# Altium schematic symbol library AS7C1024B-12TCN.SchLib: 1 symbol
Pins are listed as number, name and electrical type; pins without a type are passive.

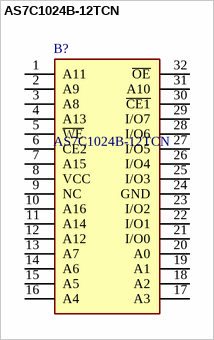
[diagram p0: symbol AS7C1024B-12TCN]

## AS7C1024B-12TCN
designator B?
Industrial and commercial temperatures  Organization: 131,072 words x 8 bits  High speed  10/12/15/20 ns address access time  5/6/7/8 ns output enable access time  Low power consumption: ACTIVE  605 mW / max @ 10 ns  Low power consumption: STANDBY  55 mW / max CMOS  Easy memory expansion with CE1, CE2, OE inputs  TTL/LVTTL-compatible, three-state I/O 32-pin JEDEC standard packages; Manufacturer_Name: Alliance Memory; Geometry.Height: 1.2mm
footprint SOP50P2000X120-32N
pins: 1 A11, 2 A9, 3 A8, 4 A13, 5 ~{WE}, 6 CE2, 7 A15, 8 VCC, 9 NC, 10 A16, 11 A14, 12 A12, 13 A7, 14 A6, 15 A5, 16 A4, 17 A3, 18 A2, 19 A1, 20 A0, 21 I/O0, 22 I/O1, 23 I/O2, 24 GND, 25 I/O3, 26 I/O4, 27 I/O5, 28 I/O6, 29 I/O7, 30 ~{CE1}, 31 A10, 32 ~{OE}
